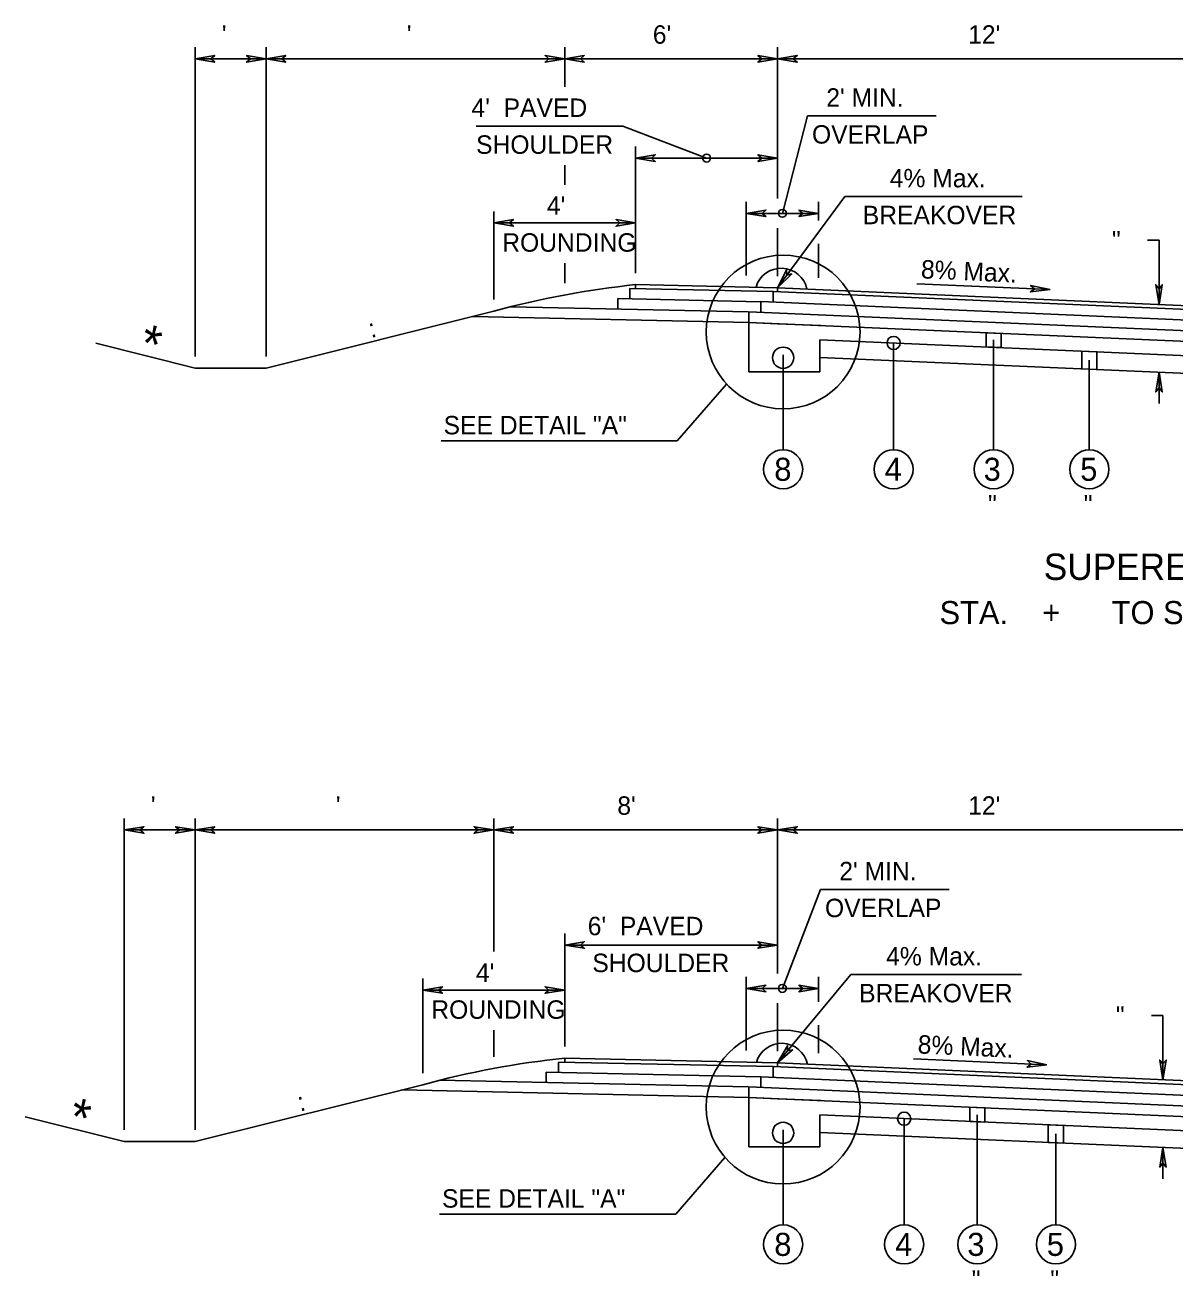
# Model space of a CAD drawing. Extents: x -592 to 1199, y -590 to 416.
# Drawn here: x 1004.6 to 1091.9, y 111.5 to 206.5 of the extents above; entities that cross this region are included whole.
import ezdxf

# ---------------------------------------------------------------- set-up
doc = ezdxf.new("R2010")
doc.units = 0
doc.layers.add('1', color=7, linetype='Continuous')
doc.layers.add('Des_ Drain_ Ftrs', color=7, linetype='Continuous')

msp = doc.modelspace()

# ---------------------------------------------------------------- linework, layer by layer
at = {"layer": '1'}
for p, q in [((1017.484, 181.295), (1017.484, 204.768)), ((1022.872, 181.295), (1022.872, 204.768)), ((1045.538, 201.76), (1045.538, 204.768)), ((1061.702, 193.288), (1061.702, 204.768)), ((1022.872, 203.888), (1017.484, 203.888)), ((1045.538, 203.888), (1022.872, 203.888)), ((1061.702, 203.888), (1045.538, 203.888)), ((1094.032, 203.888), (1061.702, 203.888)), ((1062.07, 192.16), (1063.979, 199.556)), ((1073.744, 199.556), (1063.979, 199.556)), ((1038.812, 198.781), (1049.953, 198.781)), ((1056.314, 196.357), (1049.953, 198.781)), ((1050.926, 187.626), (1050.926, 197.237)), ((1045.538, 194.332), (1045.538, 195.82)), ((1061.702, 196.357), (1050.926, 196.357)), ((1059.327, 187.443), (1059.327, 193.04)), ((1061.696, 186.511), (1066.802, 193.436)), ((1064.813, 191.619), (1064.813, 193.04)), ((1080.277, 193.436), (1066.802, 193.436)), ((1040.149, 185.615), (1040.149, 192.313)), ((1064.813, 192.16), (1059.327, 192.16)), ((1050.926, 191.433), (1040.149, 191.433)), ((1061.702, 187.391), (1061.702, 191.031)), ((1090.666, 190.125), (1089.786, 190.125)), ((1090.666, 190.125), (1090.666, 185.246)), ((1064.813, 187.255), (1064.813, 189.849)), ((1045.538, 186.849), (1045.538, 188.384)), ((1050.496, 186.455), (1061.349, 186.225)), ((1050.496, 185.669), (1050.496, 186.455)), ((1050.926, 186.746), (1061.696, 186.511)), ((1050.926, 186.746), (1050.926, 186.446)), ((1094.032, 184.799), (1061.356, 186.226)), ((1061.356, 185.417), (1061.356, 186.226)), ((1094.032, 185.099), (1061.696, 186.511)), ((1061.696, 186.511), (1061.696, 186.211)), ((1072.283, 186.815), (1082.395, 186.374)), ((1049.569, 185.69), (1060.406, 185.453)), ((1049.569, 184.898), (1049.569, 185.69)), ((1094.032, 183.99), (1060.434, 185.457)), ((1060.434, 184.648), (1060.434, 185.457)), ((1040.15, 184.735), (1022.872, 180.415)), ((1038.554, 184.336), (1059.511, 183.879)), ((1041.447, 185.075), (1059.465, 184.682)), ((1094.032, 183.181), (1059.511, 184.688)), ((1059.511, 183.879), (1059.511, 184.688)), ((1094.032, 182.372), (1059.511, 183.879)), ((1059.511, 180.124), (1059.511, 183.879)), ((1059.511, 183.879), (1061.697, 183.783)), ((1061.697, 183.783), (1064.995, 183.639)), ((1094.032, 181.293), (1064.9, 182.565)), ((1064.9, 180.124), (1064.9, 182.565)), ((1078.104, 182.557), (1078.104, 174.213)), ((1009.949, 182.299), (1017.484, 180.415)), ((1062.125, 181.429), (1062.125, 174.213)), ((1062.13, 181.429), (1062.13, 181.429)), ((1070.512, 182.32), (1070.512, 174.213)), ((1094.032, 179.945), (1064.9, 181.217)), ((1085.373, 181.002), (1085.373, 174.213)), ((1022.872, 180.415), (1017.484, 180.415)), ((1064.9, 180.124), (1059.511, 180.124)), ((1090.666, 180.094), (1090.666, 177.726)), ((1054.09, 174.876), (1057.83, 179.196)), ((1036.158, 174.876), (1054.09, 174.876)), ((1012.095, 122.563), (1012.095, 146.223)), ((1017.483, 145.343), (1012.095, 145.343)), ((1017.483, 122.563), (1017.483, 146.223)), ((1040.149, 145.343), (1017.483, 145.343)), ((1040.149, 136.123), (1040.149, 146.223)), ((1061.702, 145.343), (1040.149, 145.343)), ((1061.702, 134.438), (1061.702, 146.223)), ((1094.032, 145.343), (1061.702, 145.343)), ((1062.07, 133.31), (1064.965, 140.823)), ((1074.73, 140.823), (1064.965, 140.823)), ((1045.538, 128.894), (1045.538, 137.486)), ((1061.702, 136.606), (1045.538, 136.606)), ((1034.761, 126.883), (1034.761, 134.07)), ((1059.327, 128.593), (1059.327, 134.19)), ((1061.696, 127.661), (1067.254, 134.356)), ((1064.813, 132.293), (1064.813, 134.19)), ((1080.224, 134.356), (1067.254, 134.356)), ((1045.538, 133.19), (1034.761, 133.19)), ((1064.813, 133.31), (1059.327, 133.31)), ((1061.702, 128.541), (1061.702, 132.182)), ((1090.964, 131.262), (1090.084, 131.262)), ((1090.964, 131.262), (1090.964, 126.383)), ((1040.149, 128.117), (1040.149, 130.149)), ((1064.813, 128.405), (1064.813, 130.513)), ((1045.064, 127.724), (1061.349, 127.375)), ((1045.064, 126.939), (1045.064, 127.724)), ((1045.538, 128.014), (1061.696, 127.661)), ((1045.538, 128.014), (1045.538, 127.714)), ((1094.032, 125.949), (1061.356, 127.376)), ((1061.356, 126.567), (1061.356, 127.376)), ((1094.032, 126.249), (1061.696, 127.661)), ((1061.696, 127.661), (1061.696, 127.361)), ((1072.034, 127.962), (1082.147, 127.52)), ((1036.059, 126.343), (1059.466, 125.832)), ((1044.136, 126.959), (1060.407, 126.604)), ((1044.136, 126.167), (1044.136, 126.959)), ((1094.032, 125.14), (1060.434, 126.607)), ((1060.434, 125.798), (1060.434, 126.607)), ((1034.761, 126.003), (1017.483, 121.683)), ((1033.165, 125.604), (1059.511, 125.029)), ((1094.032, 124.331), (1059.511, 125.838)), ((1059.511, 125.029), (1059.511, 125.838)), ((1059.511, 121.274), (1059.511, 125.029)), ((1094.032, 123.522), (1059.511, 125.029)), ((1059.511, 125.029), (1061.697, 124.933)), ((1061.697, 124.934), (1064.995, 124.79)), ((1004.56, 123.567), (1012.095, 121.683)), ((1094.032, 122.443), (1064.9, 123.715)), ((1064.9, 121.274), (1064.9, 123.715)), ((1076.867, 123.711), (1076.867, 115.363)), ((1062.125, 122.58), (1062.125, 115.363)), ((1062.13, 122.58), (1062.13, 122.58)), ((1071.312, 123.42), (1071.312, 115.363)), ((1017.483, 121.683), (1012.095, 121.683)), ((1094.032, 121.095), (1064.9, 122.367)), ((1082.835, 122.281), (1082.835, 115.363)), ((1064.9, 121.274), (1059.511, 121.274)), ((1090.964, 121.231), (1090.964, 118.863)), ((1053.968, 116.163), (1057.708, 120.483)), ((1036.037, 116.163), (1053.968, 116.163))]:
    msp.add_line(p, q, dxfattribs=at)
for points in [[(1077.531, 183.092), (1078.678, 183.042), (1078.678, 181.964), (1077.531, 182.014)], [(1084.799, 181.696), (1085.946, 181.646), (1085.946, 180.298), (1084.799, 180.348)], [(1076.294, 124.296), (1077.44, 124.246), (1077.44, 123.168), (1076.294, 123.218)], [(1082.261, 122.957), (1083.408, 122.907), (1083.408, 121.559), (1082.261, 121.609)]]:
    msp.add_lwpolyline(points, close=True, dxfattribs=at)
for centre, radius in [((1056.314, 196.357), 0.3), ((1062.07, 192.16), 0.3), ((1062.123, 183.152), 5.838), ((1070.512, 182.32), 0.5), ((1062.125, 181.194), 0.808), ((1062.125, 172.727), 1.485), ((1070.512, 172.727), 1.485), ((1078.104, 172.727), 1.485), ((1085.373, 172.727), 1.485), ((1062.07, 133.31), 0.3), ((1062.123, 124.302), 5.838), ((1071.312, 123.42), 0.5), ((1062.125, 122.345), 0.808), ((1062.125, 113.878), 1.485), ((1071.312, 113.878), 1.485), ((1076.867, 113.878), 1.485), ((1082.835, 113.878), 1.485)]:
    msp.add_circle(centre, radius, dxfattribs=at)
for centre, radius, start, end in [((1061.981, 185.996), 1.997, 12.08299, 163.60416), ((1057.822, 119.913), 67.188, 95.89109, 105.24966), ((1062.012, 127.147), 1.997, 12.00196, 164.02792), ((1052.432, 61.181), 67.188, 95.88973, 105.24829)]:
    msp.add_arc(centre, radius, start, end, dxfattribs=at)
at = {"layer": 'Des_ Drain_ Ftrs'}
for points in [[(1017.484, 203.888), (1018.972, 203.64), (1018.677, 203.888), (1018.972, 204.136)], [(1022.872, 203.888), (1021.384, 203.64), (1021.679, 203.888), (1021.384, 204.136)], [(1022.872, 203.888), (1024.36, 203.64), (1024.065, 203.888), (1024.36, 204.136)], [(1045.538, 203.888), (1044.049, 203.64), (1044.344, 203.888), (1044.049, 204.136)], [(1045.538, 203.888), (1047.026, 203.64), (1046.731, 203.888), (1047.026, 204.136)], [(1061.702, 203.888), (1060.214, 203.64), (1060.509, 203.888), (1060.214, 204.136)], [(1061.702, 203.888), (1063.191, 203.64), (1062.896, 203.888), (1063.191, 204.136)], [(1050.926, 196.357), (1052.414, 196.108), (1052.119, 196.357), (1052.414, 196.605)], [(1061.702, 196.357), (1060.214, 196.108), (1060.509, 196.357), (1060.214, 196.605)], [(1059.327, 192.16), (1060.815, 191.911), (1060.52, 192.16), (1060.815, 192.408)], [(1064.813, 192.16), (1063.324, 191.911), (1063.619, 192.16), (1063.324, 192.408)], [(1040.149, 191.433), (1041.638, 191.185), (1041.343, 191.433), (1041.638, 191.681)], [(1050.926, 191.433), (1049.437, 191.185), (1049.732, 191.433), (1049.437, 191.681)], [(1061.696, 186.511), (1062.779, 187.562), (1062.404, 187.472), (1062.379, 187.856)], [(1082.395, 186.374), (1080.898, 186.19), (1081.203, 186.426), (1080.919, 186.687)], [(1090.666, 185.246), (1090.915, 186.735), (1090.666, 186.44), (1090.418, 186.735)], [(1090.666, 180.094), (1090.915, 178.606), (1090.666, 178.901), (1090.418, 178.606)], [(1012.095, 145.343), (1013.583, 145.095), (1013.288, 145.343), (1013.583, 145.592)], [(1017.483, 145.343), (1015.995, 145.095), (1016.29, 145.343), (1015.995, 145.592)], [(1017.483, 145.343), (1018.971, 145.095), (1018.676, 145.343), (1018.971, 145.592)], [(1040.149, 145.343), (1038.661, 145.095), (1038.956, 145.343), (1038.661, 145.592)], [(1040.149, 145.343), (1041.638, 145.095), (1041.343, 145.343), (1041.638, 145.592)], [(1061.702, 145.343), (1060.214, 145.095), (1060.509, 145.343), (1060.214, 145.592)], [(1061.702, 145.343), (1063.191, 145.095), (1062.896, 145.343), (1063.191, 145.592)], [(1045.538, 136.606), (1047.026, 136.358), (1046.731, 136.606), (1047.026, 136.854)], [(1061.702, 136.606), (1060.214, 136.358), (1060.509, 136.606), (1060.214, 136.854)], [(1034.761, 133.19), (1036.249, 132.942), (1035.954, 133.19), (1036.249, 133.438)], [(1045.538, 133.19), (1044.049, 132.942), (1044.344, 133.19), (1044.049, 133.438)], [(1059.327, 133.31), (1060.815, 133.062), (1060.52, 133.31), (1060.815, 133.558)], [(1064.813, 133.31), (1063.324, 133.062), (1063.619, 133.31), (1063.324, 133.558)], [(1061.696, 127.661), (1062.838, 128.648), (1062.458, 128.579), (1062.456, 128.965)], [(1082.147, 127.52), (1080.649, 127.337), (1080.955, 127.573), (1080.671, 127.833)], [(1090.964, 126.383), (1091.212, 127.872), (1090.964, 127.577), (1090.715, 127.872)], [(1090.964, 121.231), (1091.212, 119.743), (1090.964, 120.038), (1090.715, 119.743)]]:
    msp.add_lwpolyline(points, close=True, dxfattribs=at)

# ---------------------------------------------------------------- texts
at = {"layer": '1'}
for s, height, p in [(" '", 1.4, (1018.983, 205.039)), ("  '", 1.4, (1032.509, 205.039)), ("6'", 1.4, (1052.23, 205.039)), ("12'", 1.4, (1076.173, 205.039)), ("2' MIN.", 1.4, (1065.404, 200.256)), ("4'  PAVED", 1.4, (1038.461, 199.481)), ('OVERLAP', 1.4, (1064.314, 197.456)), ('SHOULDER', 1.4, (1038.81, 196.681)), ('4% Max.', 1.4, (1070.223, 194.136)), ("4'", 1.4, (1044.185, 192.049)), ('BREAKOVER', 1.4, (1068.172, 191.336)), ('ROUNDING', 1.4, (1040.796, 189.249)), ('SEE DETAIL "A"', 1.4, (1036.343, 175.38)), ('8', 1.75, (1061.452, 171.852)), ('4', 1.75, (1069.836, 171.852)), ('3', 1.75, (1077.348, 171.852)), ('5', 1.75, (1084.682, 171.853)), (' "', 1.4, (1077.161, 169.368)), (' "', 1.4, (1084.429, 169.368)), ('SUPERELEVATED', 2, (1081.912, 164.329)), ('STA.    +      TO STA.    +     ', 1.75, (1074.002, 160.973)), (" '", 1.4, (1013.594, 146.494)), ("  '", 1.4, (1027.12, 146.494)), ("8'", 1.4, (1049.535, 146.494)), ("12'", 1.4, (1076.173, 146.494)), ("2' MIN.", 1.4, (1066.39, 141.523)), ('OVERLAP', 1.4, (1065.301, 138.723)), ("6'  PAVED", 1.4, (1047.287, 137.35)), ('SHOULDER', 1.4, (1047.636, 134.55)), ('4% Max.', 1.4, (1069.945, 135.056)), ("4'", 1.4, (1038.797, 133.806)), ('BREAKOVER', 1.4, (1067.895, 132.256)), ('ROUNDING', 1.4, (1035.408, 131.006)), ('SEE DETAIL "A"', 1.4, (1036.222, 116.666)), ('8', 1.75, (1061.452, 113.003)), ('4', 1.75, (1070.636, 113.003)), ('3', 1.75, (1076.111, 113.003)), ('5', 1.75, (1082.144, 113.003)), (' "', 1.4, (1075.923, 110.518)), (' "', 1.4, (1081.891, 110.518))]:
    msp.add_text(s, height=height, dxfattribs=at).set_placement(p)
for s, height, rotation, p in [('  "', 1.4, 0.14377, (1086.054, 189.422)), ('8% Max.', 1.4, 357.3764, (1072.565, 187.231)), ('*', 2.8, 347.15207, (1013.115, 181.06)), (' : ', 1.4, 14.22821, (1030.331, 182.562)), ('  "', 1.4, 0.14377, (1086.351, 130.559)), ('8% Max.', 1.4, 357.37622, (1072.316, 128.378)), ('*', 2.8, 347.15207, (1007.726, 122.328)), (' : ', 1.4, 14.22821, (1024.942, 123.83))]:
    msp.add_text(s, height=height, rotation=rotation, dxfattribs=at).set_placement(p)

doc.saveas('drawing.dxf')
